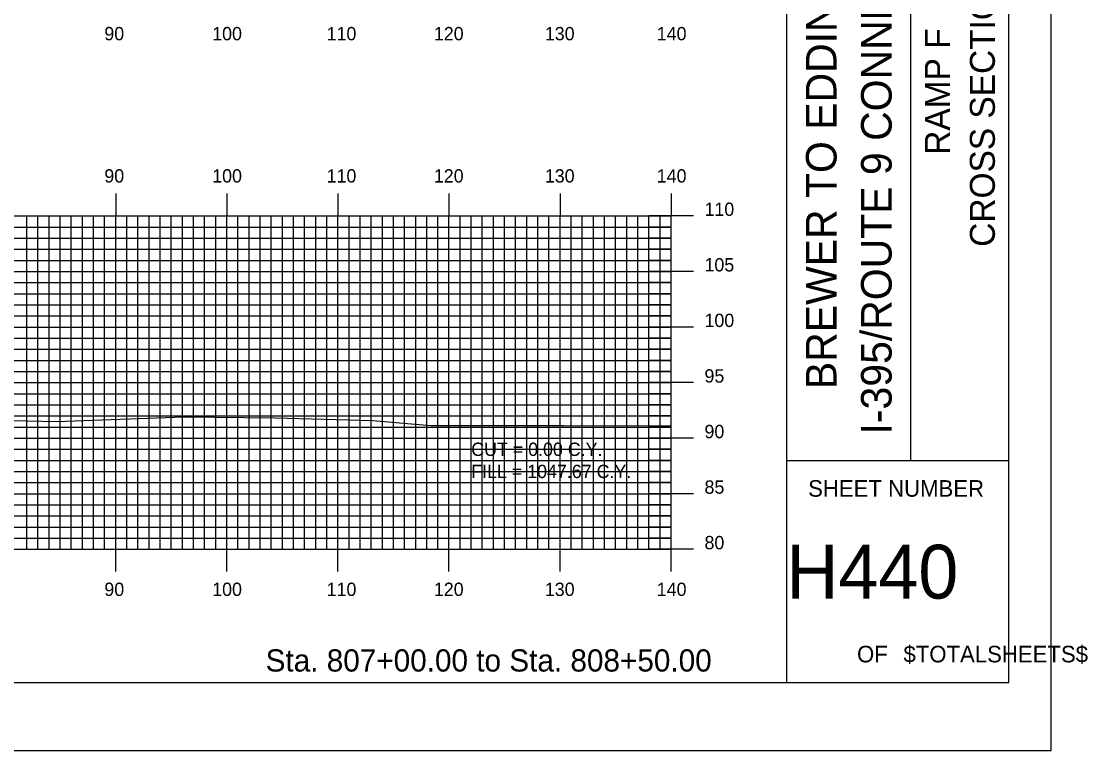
# Model space of a CAD drawing. Extents: x 1272 to 1616, y -1658 to -1438.
# Drawn here: x 1519.7 to 1615.7, y -1657.7 to -1592.1 of the extents above; entities that cross this region are included whole.
import ezdxf

# ---------------------------------------------------------------- set-up
doc = ezdxf.new("R2010")
doc.units = 0
for name, color, linetype in [('BORDER', 7, 'Continuous'), ('D_Text_Standard', 7, 'Continuous'), ('H_V ANNOTATION', 7, 'Continuous'), ('MAJOR', 7, 'Continuous'), ('MINOR', 7, 'Continuous'), ('PLOT BOUNDARY', 7, 'Continuous'), ('S_Roadway_Centerline', 7, 'Continuous')]:
    doc.layers.add(name, color=color, linetype=linetype)

msp = doc.modelspace()

# ---------------------------------------------------------------- linework, layer by layer
at = {"layer": 'BORDER'}
for p, q in [((1588.561, -1651.604), (1588.561, -1441.604)), ((1599.743, -1631.599), (1599.743, -1561.599)), ((1588.561, -1631.599), (1608.561, -1631.599))]:
    msp.add_line(p, q, dxfattribs=at)
msp.add_lwpolyline([(1288.561, -1651.604), (1608.561, -1651.604), (1608.561, -1441.604), (1288.561, -1441.604)], close=True, dxfattribs=at)
at = {"layer": 'MAJOR'}
for p, q in [((1528.161, -1607.6), (1528.161, -1609.604)), ((1538.161, -1607.6), (1538.161, -1609.604)), ((1548.161, -1607.6), (1548.161, -1609.604)), ((1558.161, -1607.6), (1558.161, -1609.604)), ((1568.161, -1607.6), (1568.161, -1609.604)), ((1578.161, -1607.6), (1578.161, -1609.604)), ((1298.161, -1609.604), (1578.161, -1609.604)), ((1298.161, -1609.604), (1578.161, -1609.604)), ((1528.161, -1639.604), (1528.161, -1609.604)), ((1538.161, -1639.604), (1538.161, -1609.604)), ((1548.161, -1639.604), (1548.161, -1609.604)), ((1558.161, -1639.604), (1558.161, -1609.604)), ((1568.161, -1639.604), (1568.161, -1609.604)), ((1580.165, -1609.604), (1576.157, -1609.604)), ((1578.161, -1639.604), (1578.161, -1609.604)), ((1578.161, -1639.604), (1578.161, -1609.604)), ((1298.161, -1614.604), (1578.161, -1614.604)), ((1580.165, -1614.604), (1576.157, -1614.604)), ((1298.161, -1619.604), (1578.161, -1619.604)), ((1580.165, -1619.604), (1576.157, -1619.604)), ((1298.161, -1624.604), (1578.161, -1624.604)), ((1580.165, -1624.604), (1576.157, -1624.604)), ((1298.161, -1629.604), (1578.161, -1629.604)), ((1580.165, -1629.604), (1576.157, -1629.604)), ((1298.161, -1634.604), (1578.161, -1634.604)), ((1580.165, -1634.604), (1576.157, -1634.604)), ((1298.161, -1639.604), (1578.161, -1639.604)), ((1298.161, -1639.604), (1578.161, -1639.604)), ((1528.161, -1641.608), (1528.161, -1639.604)), ((1538.161, -1641.608), (1538.161, -1639.604)), ((1548.161, -1641.608), (1548.161, -1639.604)), ((1558.161, -1641.608), (1558.161, -1639.604)), ((1568.161, -1641.608), (1568.161, -1639.604)), ((1580.165, -1639.604), (1576.157, -1639.604)), ((1578.161, -1641.608), (1578.161, -1639.604))]:
    msp.add_line(p, q, dxfattribs=at)
at = {"layer": 'MINOR'}
for p, q in [((1520.161, -1639.604), (1520.161, -1609.604)), ((1521.161, -1639.604), (1521.161, -1609.604)), ((1522.161, -1639.604), (1522.161, -1609.604)), ((1523.161, -1639.604), (1523.161, -1609.604)), ((1524.161, -1639.604), (1524.161, -1609.604)), ((1525.161, -1639.604), (1525.161, -1609.604)), ((1526.161, -1639.604), (1526.161, -1609.604)), ((1527.161, -1639.604), (1527.161, -1609.604)), ((1529.161, -1639.604), (1529.161, -1609.604)), ((1530.161, -1639.604), (1530.161, -1609.604)), ((1531.161, -1639.604), (1531.161, -1609.604)), ((1532.161, -1639.604), (1532.161, -1609.604)), ((1533.161, -1639.604), (1533.161, -1609.604)), ((1534.161, -1639.604), (1534.161, -1609.604)), ((1535.161, -1639.604), (1535.161, -1609.604)), ((1536.161, -1639.604), (1536.161, -1609.604)), ((1537.161, -1639.604), (1537.161, -1609.604)), ((1539.161, -1639.604), (1539.161, -1609.604)), ((1540.161, -1639.604), (1540.161, -1609.604)), ((1541.161, -1639.604), (1541.161, -1609.604)), ((1542.161, -1639.604), (1542.161, -1609.604)), ((1543.161, -1639.604), (1543.161, -1609.604)), ((1544.161, -1639.604), (1544.161, -1609.604)), ((1545.161, -1639.604), (1545.161, -1609.604)), ((1546.161, -1639.604), (1546.161, -1609.604)), ((1547.161, -1639.604), (1547.161, -1609.604)), ((1549.161, -1639.604), (1549.161, -1609.604)), ((1550.161, -1639.604), (1550.161, -1609.604)), ((1551.161, -1639.604), (1551.161, -1609.604)), ((1552.161, -1639.604), (1552.161, -1609.604)), ((1553.161, -1639.604), (1553.161, -1609.604)), ((1554.161, -1639.604), (1554.161, -1609.604)), ((1555.161, -1639.604), (1555.161, -1609.604)), ((1556.161, -1639.604), (1556.161, -1609.604)), ((1557.161, -1639.604), (1557.161, -1609.604)), ((1559.161, -1639.604), (1559.161, -1609.604)), ((1560.161, -1639.604), (1560.161, -1609.604)), ((1561.161, -1639.604), (1561.161, -1609.604)), ((1562.161, -1639.604), (1562.161, -1609.604)), ((1563.161, -1639.604), (1563.161, -1609.604)), ((1564.161, -1639.604), (1564.161, -1609.604)), ((1565.161, -1639.604), (1565.161, -1609.604)), ((1566.161, -1639.604), (1566.161, -1609.604)), ((1567.161, -1639.604), (1567.161, -1609.604)), ((1569.161, -1639.604), (1569.161, -1609.604)), ((1570.161, -1639.604), (1570.161, -1609.604)), ((1571.161, -1639.604), (1571.161, -1609.604)), ((1572.161, -1639.604), (1572.161, -1609.604)), ((1573.161, -1639.604), (1573.161, -1609.604)), ((1574.161, -1639.604), (1574.161, -1609.604)), ((1575.161, -1639.604), (1575.161, -1609.604)), ((1576.161, -1639.604), (1576.161, -1609.604)), ((1577.161, -1639.604), (1577.161, -1609.604)), ((1298.161, -1610.604), (1578.161, -1610.604)), ((1578.161, -1610.604), (1576.157, -1610.604)), ((1298.161, -1611.604), (1578.161, -1611.604)), ((1578.161, -1611.604), (1576.157, -1611.604)), ((1298.161, -1612.604), (1578.161, -1612.604)), ((1578.161, -1612.604), (1576.157, -1612.604)), ((1298.161, -1613.604), (1578.161, -1613.604)), ((1578.161, -1613.604), (1576.157, -1613.604)), ((1298.161, -1615.604), (1578.161, -1615.604)), ((1578.161, -1615.604), (1576.157, -1615.604)), ((1298.161, -1616.604), (1578.161, -1616.604)), ((1578.161, -1616.604), (1576.157, -1616.604)), ((1298.161, -1617.604), (1578.161, -1617.604)), ((1578.161, -1617.604), (1576.157, -1617.604)), ((1298.161, -1618.604), (1578.161, -1618.604)), ((1578.161, -1618.604), (1576.157, -1618.604)), ((1298.161, -1620.604), (1578.161, -1620.604)), ((1578.161, -1620.604), (1576.157, -1620.604)), ((1298.161, -1621.604), (1578.161, -1621.604)), ((1578.161, -1621.604), (1576.157, -1621.604)), ((1298.161, -1622.604), (1578.161, -1622.604)), ((1578.161, -1622.604), (1576.157, -1622.604)), ((1298.161, -1623.604), (1578.161, -1623.604)), ((1578.161, -1623.604), (1576.157, -1623.604)), ((1298.161, -1625.604), (1578.161, -1625.604)), ((1578.161, -1625.604), (1576.157, -1625.604)), ((1298.161, -1626.604), (1578.161, -1626.604)), ((1578.161, -1626.604), (1576.157, -1626.604)), ((1298.161, -1627.604), (1578.161, -1627.604)), ((1578.161, -1627.604), (1576.157, -1627.604)), ((1298.161, -1628.604), (1578.161, -1628.604)), ((1578.161, -1628.604), (1576.157, -1628.604)), ((1298.161, -1630.604), (1578.161, -1630.604)), ((1578.161, -1630.604), (1576.157, -1630.604)), ((1298.161, -1631.604), (1578.161, -1631.604)), ((1578.161, -1631.604), (1576.157, -1631.604)), ((1298.161, -1632.604), (1578.161, -1632.604)), ((1578.161, -1632.604), (1576.157, -1632.604)), ((1298.161, -1633.604), (1578.161, -1633.604)), ((1578.161, -1633.604), (1576.157, -1633.604)), ((1298.161, -1635.604), (1578.161, -1635.604)), ((1578.161, -1635.604), (1576.157, -1635.604)), ((1298.161, -1636.604), (1578.161, -1636.604)), ((1578.161, -1636.604), (1576.157, -1636.604)), ((1298.161, -1637.604), (1578.161, -1637.604)), ((1578.161, -1637.604), (1576.157, -1637.604)), ((1298.161, -1638.604), (1578.161, -1638.604)), ((1578.161, -1638.604), (1576.157, -1638.604))]:
    msp.add_line(p, q, dxfattribs=at)
at = {"layer": 'PLOT BOUNDARY'}
msp.add_lwpolyline([(1272.374, -1657.723), (1612.374, -1657.723), (1612.374, -1437.723), (1272.374, -1437.723)], close=True, dxfattribs=at)
at = {"layer": 'S_Roadway_Centerline'}
msp.add_lwpolyline([(1418.672, -1629.531), (1427.203, -1629.296), (1434.214, -1629.045), (1441.66, -1628.984), (1450.981, -1628.982), (1462.096, -1629.094), (1467.317, -1629.066), (1470.882, -1628.94), (1484.74, -1628.348), (1492.166, -1628.114), (1501.084, -1627.871), (1513.6, -1628.089), (1517.414, -1627.97), (1522.861, -1628.103), (1534.278, -1627.697), (1542.479, -1627.762), (1551.3, -1628.017), (1556.518, -1628.462), (1568.503, -1628.468), (1578.161, -1628.496)], dxfattribs=at)

# ---------------------------------------------------------------- texts
at = {"layer": 'BORDER'}
for s, height, p in [('BREWER TO EDDINGTON', 2.75575, (1593.049, -1625.195)), ('I-395/ROUTE 9 CONNECTOR', 2.75575, (1598.01, -1629.274)), ('CROSS SECTIONS', 2.25, (1607.302, -1612.383)), ('RAMP F', 2.25, (1603.252, -1604.101))]:
    msp.add_text(s, height=height, rotation=90, dxfattribs=at).set_placement(p)
for s, height, p in [('SHEET NUMBER', 1.49054, (1590.491, -1634.872)), ('H440', 4.8388, (1588.542, -1644.039)), ('$TOTALSHEETS$', 1.49054, (1599.073, -1649.779)), ('OF', 1.4905, (1594.894, -1649.779))]:
    msp.add_text(s, height=height, dxfattribs=at).set_placement(p)
at = {"layer": 'D_Text_Standard'}
for s, p in [('CUT = 0.00 C.Y.', (1560.161, -1631.204)), ('FILL = 1047.67 C.Y.', (1560.161, -1633.196))]:
    msp.add_text(s, height=1.2, dxfattribs=at).set_placement(p)
at = {"layer": 'H_V ANNOTATION'}
for s, height, p in [('90', 1.2, (1527.133, -1593.804)), ('100', 1.2, (1536.844, -1593.804)), ('110', 1.2, (1547.144, -1593.804)), ('120', 1.2, (1556.801, -1593.804)), ('130', 1.2, (1566.79, -1593.804)), ('140', 1.2, (1576.865, -1593.804)), ('90', 1.2, (1527.133, -1606.604)), ('100', 1.2, (1536.844, -1606.604)), ('110', 1.2, (1547.144, -1606.604)), ('120', 1.2, (1556.801, -1606.604)), ('130', 1.2, (1566.79, -1606.604)), ('140', 1.2, (1576.865, -1606.604)), ('110', 1.2, (1581.161, -1609.604)), ('105', 1.2, (1581.161, -1614.604)), ('100', 1.2, (1581.161, -1619.604)), ('95', 1.2, (1581.161, -1624.604)), ('90', 1.2, (1581.161, -1629.604)), ('85', 1.2, (1581.161, -1634.604)), ('80', 1.2, (1581.161, -1639.604)), ('90', 1.2, (1527.133, -1643.804)), ('100', 1.2, (1536.844, -1643.804)), ('110', 1.2, (1547.144, -1643.804)), ('120', 1.2, (1556.801, -1643.804)), ('130', 1.2, (1566.79, -1643.804)), ('140', 1.2, (1576.865, -1643.804)), ('Sta. 807+00.00 to Sta. 808+50.00', 2.0004, (1541.652, -1650.605))]:
    msp.add_text(s, height=height, dxfattribs=at).set_placement(p)

doc.saveas('drawing.dxf')
